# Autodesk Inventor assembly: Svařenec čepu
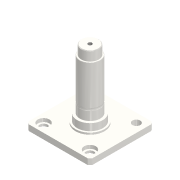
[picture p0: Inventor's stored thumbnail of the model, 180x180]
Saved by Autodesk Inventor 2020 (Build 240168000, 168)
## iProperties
Created: 2025-03
Part Number: Svařenec čepu
Document SubType Name: Assembly
Designer: doma
Mass: 1892.47 g
Surface Area: 485.923 cm^2
Volume: 241.078 cm^3
Density: 7.85 g/cm^3
Author: doma
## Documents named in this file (3)
- C:\Users\doma\Desktop\Pásovka záloha\Workgroups\NotInProject\Svařenec čepu.iam
- C:\Users\doma\Desktop\Pásovka záloha\Workgroups\NotInProject\Čep.ipt
- C:\Users\doma\Desktop\Pásovka záloha\Workgroups\NotInProject\Deska čepu.ipt
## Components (2 placed, 2 different names)
1. Čep:1 — Proti sobě:1, Proti sobě:2, Úhel:1
2. Deska čepu:1 — Proti sobě:1, Proti sobě:2, Úhel:1
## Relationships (3: Mate 2, Angle 1)
- Proti sobě:1 [Mate]: Čep:1 ↔ Deska čepu:1
- Proti sobě:2 [Mate]: Čep:1 ↔ Deska čepu:1
- Úhel:1 [Angle]: Čep:1 ↔ Deska čepu:1
